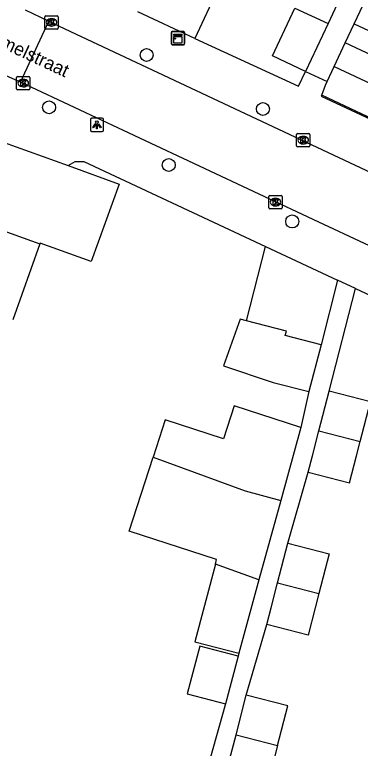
# Model space of a CAD drawing. Extents: x 159822 to 160765, y 380693 to 381634.
# Drawn here: x 160181.4 to 160207.5, y 381227.9 to 381283.3 of the extents above; entities that cross this region are included whole.
import ezdxf

# ---------------------------------------------------------------- set-up
doc = ezdxf.new("R2010")
doc.units = 0
for name, color, linetype in [('IMGEO_Boom', 7, 'Continuous'), ('IMGEO_Kast', 7, 'Continuous'), ('IMGEO_Kolk', 7, 'Continuous'), ('IMGEO_Lichtpunt', 7, 'Continuous'), ('IMGEO_Muur', 7, 'Continuous'), ('IMGEO_Openbare_ruimte_label', 7, 'Continuous'), ('IMGEO_Pand', 7, 'Continuous'), ('IMGEO_Rijbaan_lokaal_open', 7, 'Continuous'), ('IMGEO_Voetpad_halfverhard', 7, 'Continuous'), ('IMGEO_Voetpad_open', 7, 'Continuous')]:
    doc.layers.add(name, color=color, linetype=linetype)

msp = doc.modelspace()

# ---------------------------------------------------------------- linework, layer by layer
at = {"layer": 'IMGEO_Boom'}
for centre in [(160191.397, 381280.228), (160184.034, 381276.28), (160200.168, 381276.158), (160193.06, 381271.931), (160202.378, 381267.672)]:
    msp.add_circle(centre, 0.489, dxfattribs=at)
at = {"layer": 'IMGEO_Kast'}
for p, q in [((160193.337, 381282.002), (160194.178, 381282.002)), ((160194.178, 381282.002), (160193.337, 381282.002)), ((160193.262, 381281.077), (160193.262, 381281.918)), ((160193.262, 381281.918), (160193.262, 381281.077)), ((160194.262, 381281.927), (160194.262, 381281.086)), ((160194.262, 381281.086), (160194.262, 381281.927)), ((160194.187, 381281.002), (160193.346, 381281.002)), ((160193.346, 381281.002), (160194.187, 381281.002))]:
    msp.add_line(p, q, dxfattribs=at)
for points in [[(160193.457, 381281.792), (160194.057, 381281.792), (160194.057, 381281.707), (160193.457, 381281.707), (160193.457, 381281.792)], [(160193.457, 381281.617), (160194.057, 381281.617), (160194.057, 381281.128), (160193.457, 381281.128), (160193.457, 381281.617)]]:
    msp.add_lwpolyline(points, dxfattribs=at)
msp.add_circle((160193.541, 381281.466), 0.0377, dxfattribs=at)
for centre, start, end in [((160193.34, 381281.924), 92.4484, 184.2845), ((160193.34, 381281.924), 92.4484, 184.2845), ((160194.184, 381281.924), 2.4484, 94.2845), ((160194.184, 381281.924), 2.4484, 94.2845), ((160193.34, 381281.08), 182.4484, 274.2845), ((160193.34, 381281.08), 182.4484, 274.2845), ((160194.184, 381281.08), 272.4484, 4.2845), ((160194.184, 381281.08), 272.4484, 4.2845)]:
    msp.add_arc(centre, 0.0779, start, end, dxfattribs=at)
at = {"layer": 'IMGEO_Kolk'}
for p, q in [((160183.72, 381282.262), (160183.72, 381283.114)), ((160183.795, 381283.188), (160184.647, 381283.188)), ((160184.721, 381283.114), (160184.721, 381282.262)), ((160184.208, 381282.968), (160184.233, 381282.968)), ((160184.647, 381282.188), (160183.795, 381282.188)), ((160184.231, 381282.408), (160184.206, 381282.408)), ((160181.589, 381277.685), (160181.589, 381278.537)), ((160181.664, 381278.611), (160182.516, 381278.611)), ((160182.077, 381278.391), (160182.102, 381278.391)), ((160182.59, 381278.537), (160182.59, 381277.685)), ((160182.516, 381277.611), (160181.664, 381277.611)), ((160182.1, 381277.831), (160182.075, 381277.831)), ((160202.703, 381273.382), (160202.703, 381274.234)), ((160202.778, 381274.308), (160203.63, 381274.308)), ((160203.704, 381274.234), (160203.704, 381273.382)), ((160203.191, 381274.088), (160203.216, 381274.088)), ((160203.63, 381273.308), (160202.778, 381273.308)), ((160203.214, 381273.528), (160203.189, 381273.528)), ((160200.614, 381268.707), (160200.614, 381269.559)), ((160200.689, 381269.633), (160201.541, 381269.633)), ((160201.102, 381269.413), (160201.127, 381269.413)), ((160201.615, 381269.559), (160201.615, 381268.707)), ((160201.125, 381268.853), (160201.1, 381268.853)), ((160201.541, 381268.633), (160200.689, 381268.633))]:
    msp.add_line(p, q, dxfattribs=at)
for points in [[(160183.72, 381282.262), (160183.72, 381283.114)], [(160183.795, 381283.188), (160184.647, 381283.188)], [(160184.721, 381283.114), (160184.721, 381282.262)], [(160184.041, 381282.888), (160184.164, 381282.888), (160184.164, 381282.737), (160184.294, 381282.888), (160184.458, 381282.888), (160184.312, 381282.737), (160184.465, 381282.488), (160184.313, 381282.488), (160184.228, 381282.652), (160184.164, 381282.585), (160184.164, 381282.488), (160184.041, 381282.488), (160184.041, 381282.888)], [(160184.647, 381282.188), (160183.795, 381282.188)], [(160181.589, 381277.685), (160181.589, 381278.537)], [(160181.664, 381278.611), (160182.516, 381278.611)], [(160181.91, 381278.311), (160182.033, 381278.311), (160182.033, 381278.16), (160182.163, 381278.311), (160182.327, 381278.311), (160182.181, 381278.16), (160182.334, 381277.911), (160182.182, 381277.911), (160182.097, 381278.075), (160182.033, 381278.008), (160182.033, 381277.911), (160181.91, 381277.911), (160181.91, 381278.311)], [(160182.59, 381278.537), (160182.59, 381277.685)], [(160182.516, 381277.611), (160181.664, 381277.611)], [(160202.703, 381273.382), (160202.703, 381274.234)], [(160202.778, 381274.308), (160203.63, 381274.308)], [(160203.704, 381274.234), (160203.704, 381273.382)], [(160203.024, 381274.008), (160203.147, 381274.008), (160203.147, 381273.857), (160203.277, 381274.008), (160203.441, 381274.008), (160203.295, 381273.857), (160203.448, 381273.608), (160203.296, 381273.608), (160203.211, 381273.772), (160203.147, 381273.705), (160203.147, 381273.608), (160203.024, 381273.608), (160203.024, 381274.008)], [(160203.63, 381273.308), (160202.778, 381273.308)], [(160200.614, 381268.707), (160200.614, 381269.559)], [(160200.689, 381269.633), (160201.541, 381269.633)], [(160200.935, 381269.333), (160201.058, 381269.333), (160201.058, 381269.182), (160201.188, 381269.333), (160201.352, 381269.333), (160201.206, 381269.182), (160201.359, 381268.933), (160201.207, 381268.933), (160201.122, 381269.097), (160201.058, 381269.03), (160201.058, 381268.933), (160200.935, 381268.933), (160200.935, 381269.333)], [(160201.615, 381269.559), (160201.615, 381268.707)], [(160201.541, 381268.633), (160200.689, 381268.633)]]:
    msp.add_lwpolyline(points, dxfattribs=at)
for centre, start, end in [((160183.797, 381283.112), 91.552, 178.448), ((160183.797, 381283.112), 91.552, 178.448), ((160184.645, 381283.112), 1.552, 88.448), ((160184.645, 381283.112), 1.552, 88.448), ((160183.797, 381282.264), 181.552, 268.448), ((160183.797, 381282.264), 181.552, 268.448), ((160184.645, 381282.264), 271.552, 358.448), ((160184.645, 381282.264), 271.552, 358.448), ((160181.666, 381278.535), 91.552, 178.448), ((160181.666, 381278.535), 91.552, 178.448), ((160182.514, 381278.535), 1.552, 88.448), ((160182.514, 381278.535), 1.552, 88.448), ((160181.666, 381277.687), 181.552, 268.448), ((160181.666, 381277.687), 181.552, 268.448), ((160182.514, 381277.687), 271.552, 358.448), ((160182.514, 381277.687), 271.552, 358.448), ((160202.78, 381274.232), 91.552, 178.448), ((160202.78, 381274.232), 91.552, 178.448), ((160203.628, 381274.232), 1.552, 88.448), ((160203.628, 381274.232), 1.552, 88.448), ((160202.78, 381273.384), 181.552, 268.448), ((160202.78, 381273.384), 181.552, 268.448), ((160203.628, 381273.384), 271.552, 358.448), ((160203.628, 381273.384), 271.552, 358.448), ((160200.691, 381269.557), 91.552, 178.448), ((160200.691, 381269.557), 91.552, 178.448), ((160201.539, 381269.557), 1.552, 88.448), ((160201.539, 381269.557), 1.552, 88.448), ((160200.691, 381268.709), 181.552, 268.448), ((160200.691, 381268.709), 181.552, 268.448), ((160201.539, 381268.709), 271.552, 358.448), ((160201.539, 381268.709), 271.552, 358.448)]:
    msp.add_arc(centre, 0.0765, start, end, dxfattribs=at)
for centre, major_axis, ratio, start_param, end_param in [((160184.207, 381282.688), (-0.387, 0.002), 0.722429, 4.712389, 7.853982), ((160184.232, 381282.688), (-0.39, 0.002), 0.717154, 1.570796, 4.712389), ((160182.076, 381278.111), (-0.387, 0.002), 0.722429, 4.712389, 7.853982), ((160182.101, 381278.111), (-0.39, 0.002), 0.717154, 1.570796, 4.712389), ((160203.19, 381273.808), (-0.387, 0.002), 0.722429, 4.712389, 7.853982), ((160203.215, 381273.808), (-0.39, 0.002), 0.717154, 1.570796, 4.712389), ((160201.101, 381269.133), (-0.387, 0.002), 0.722429, 4.712389, 7.853982), ((160201.126, 381269.133), (-0.39, 0.002), 0.717154, 1.570796, 4.712389)]:
    msp.add_ellipse(centre, major_axis=major_axis, ratio=ratio, start_param=start_param, end_param=end_param, dxfattribs=at)
at = {"layer": 'IMGEO_Lichtpunt'}
for p, q in [((160187.15, 381275.363), (160187.15, 381274.556)), ((160187.15, 381275.363), (160187.15, 381274.556)), ((160188.052, 381275.458), (160187.244, 381275.458)), ((160188.052, 381275.458), (160187.244, 381275.458)), ((160188.146, 381274.556), (160188.146, 381275.363)), ((160188.146, 381274.556), (160188.146, 381275.363)), ((160187.244, 381274.462), (160188.052, 381274.462)), ((160187.244, 381274.462), (160188.052, 381274.462))]:
    msp.add_line(p, q, dxfattribs=at)
for points in [[(160187.524, 381275.027), (160187.563, 381274.999), (160187.375, 381274.737), (160187.337, 381274.764), (160187.524, 381275.027)], [(160187.626, 381274.979), (160187.673, 381274.979), (160187.673, 381274.657), (160187.626, 381274.657), (160187.626, 381274.979)], [(160187.736, 381274.999), (160187.774, 381275.026), (160187.961, 381274.764), (160187.922, 381274.736), (160187.736, 381274.999)]]:
    msp.add_lwpolyline(points, dxfattribs=at)
msp.add_circle((160187.649, 381275.161), 0.0994, dxfattribs=at)
for centre, start, end in [((160187.244, 381275.363), 90, 180), ((160187.244, 381275.363), 90, 180), ((160188.052, 381275.363), 0, 90), ((160188.052, 381275.363), 0, 90), ((160187.244, 381274.556), 180, 270), ((160187.244, 381274.556), 180, 270), ((160188.052, 381274.556), 270, 0), ((160188.052, 381274.556), 270, 360)]:
    msp.add_arc(centre, 0.0946, start, end, dxfattribs=at)
at = {"layer": 'IMGEO_Muur'}
msp.add_lwpolyline([(160185.472, 381271.883), (160186.017, 381272.204), (160186.65, 381272.188), (160200.361, 381265.784)], dxfattribs=at)
at = {"layer": 'IMGEO_Pand'}
for points in [[(160194.857, 381289.201), (160195.304, 381288.991), (160194.163, 381286.554), (160196.819, 381285.312), (160195.026, 381281.48)], [(160203.391, 381278.997), (160200.901, 381280.162), (160202.585, 381283.762), (160205.076, 381282.597)], [(160207.057, 381282.582), (160207.732, 381284.025)], [(160195.026, 381281.48), (160190.736, 381283.488)], [(160205.076, 381282.597), (160203.391, 381278.997)], [(160206.381, 381281.138), (160207.057, 381282.582)], [(160207.057, 381282.582), (160212.775, 381279.925)], [(160212.775, 381279.925), (160212.092, 381278.466), (160206.381, 381281.138)], [(160205.548, 381279.354), (160209.884, 381277.322), (160208.887, 381275.196), (160204.6, 381277.205)], [(160205.023, 381278.234), (160205.548, 381279.354)], [(160204.6, 381277.205), (160204.893, 381277.957), (160205.023, 381278.234)], [(160178.596, 381274.356), (160185.472, 381271.883)], [(160185.472, 381271.883), (160189.319, 381270.499), (160187.214, 381264.647), (160183.367, 381266.03), (160183.352, 381265.987)], [(160176.477, 381268.462), (160183.352, 381265.987)], [(160183.352, 381265.987), (160181.294, 381260.262)], [(160198.919, 381260.177), (160200.361, 381265.784)], [(160200.361, 381265.784), (160205.801, 381263.242)], [(160205.801, 381263.242), (160204.55, 381258.378)], [(160198.919, 381260.177), (160198.447, 381260.298), (160197.2, 381256.779), (160200.942, 381255.53), (160203.638, 381254.836)], [(160204.55, 381258.378), (160201.853, 381259.071), (160201.938, 381259.401), (160198.919, 381260.177)], [(160204.55, 381258.378), (160203.638, 381254.836)], [(160204.389, 381251.885), (160205.158, 381254.876)], [(160207.513, 381251.081), (160208.282, 381254.072), (160205.158, 381254.876)], [(160203.021, 381252.143), (160197.997, 381253.777), (160197.187, 381251.287), (160192.802, 381252.714), (160191.883, 381249.891)], [(160203.021, 381252.143), (160201.508, 381246.63)], [(160203.583, 381248.752), (160203.904, 381250), (160204.389, 381251.885)], [(160204.389, 381251.885), (160207.513, 381251.081)], [(160203.583, 381248.752), (160206.707, 381247.948), (160207.235, 381250), (160207.513, 381251.081)], [(160196.583, 381241.83), (160196.673, 381242.165), (160190.069, 381244.314), (160191.883, 381249.891)], [(160191.883, 381249.891), (160198.824, 381247.344), (160201.508, 381246.63)], [(160201.508, 381246.63), (160199.866, 381240.65)], [(160201.265, 381240.418), (160202.034, 381243.409)], [(160202.034, 381243.409), (160205.158, 381242.605), (160204.389, 381239.614)], [(160196.583, 381241.83), (160195.031, 381235.979), (160198.348, 381235.121)], [(160199.866, 381240.65), (160196.583, 381241.83)], [(160199.866, 381240.65), (160198.348, 381235.121)], [(160200.459, 381237.285), (160200.78, 381238.533), (160201.265, 381240.418)], [(160201.265, 381240.418), (160204.389, 381239.614)], [(160204.389, 381239.614), (160204.111, 381238.533), (160203.583, 381236.481), (160200.459, 381237.285)], [(160198.297, 381234.877), (160195.405, 381235.645), (160194.451, 381232.051), (160197.344, 381231.284)], [(160198.297, 381234.877), (160197.344, 381231.284)], [(160198.141, 381228.951), (160198.91, 381231.942)], [(160201.265, 381228.147), (160202.034, 381231.138), (160198.91, 381231.942)], [(160197.335, 381225.818), (160197.656, 381227.066), (160198.141, 381228.951)], [(160198.141, 381228.951), (160201.265, 381228.147)], [(160201.265, 381228.147), (160200.987, 381227.066), (160200.459, 381225.014), (160197.335, 381225.818)]]:
    msp.add_lwpolyline(points, dxfattribs=at)
at = {"layer": 'IMGEO_Rijbaan_lokaal_open'}
for points in [[(160182.232, 381283.624), (160184.006, 381282.791)], [(160181.886, 381278.181), (160184.006, 381282.791)], [(160184.006, 381282.791), (160184.802, 381282.403), (160208.794, 381271.142), (160212.221, 381269.548), (160214.775, 381268.359)], [(160181.886, 381278.181), (160180.804, 381278.668)], [(160212.641, 381263.772), (160207.826, 381266.012), (160204.38, 381267.615), (160181.886, 381278.181)]]:
    msp.add_lwpolyline(points, dxfattribs=at)
at = {"layer": 'IMGEO_Voetpad_halfverhard'}
for points in [[(160206.238, 381285.124), (160205.076, 381282.597)], [(160205.548, 381279.354), (160206.381, 381281.138)]]:
    msp.add_lwpolyline(points, dxfattribs=at)
at = {"layer": 'IMGEO_Voetpad_open'}
for points in [[(160195.026, 381281.48), (160202.862, 381277.867), (160203.391, 381278.997)], [(160203.391, 381278.997), (160205.023, 381278.234)], [(160204.6, 381277.205), (160204.565, 381277.114), (160225.954, 381267.134)], [(160185.472, 381271.883), (160186.017, 381272.204), (160186.65, 381272.188), (160200.361, 381265.784)], [(160207.149, 381262.612), (160205.801, 381263.242)], [(160205.158, 381254.876), (160207.149, 381262.612)], [(160207.149, 381262.612), (160223.562, 381254.945), (160222.893, 381253.356), (160224.405, 381252.993)], [(160203.638, 381254.836), (160203.021, 381252.143)], [(160202.034, 381243.409), (160203.583, 381248.752)], [(160198.91, 381231.942), (160200.459, 381237.285)], [(160198.348, 381235.121), (160198.297, 381234.877)], [(160197.344, 381231.284), (160195.947, 381226.279)]]:
    msp.add_lwpolyline(points, dxfattribs=at)

# ---------------------------------------------------------------- texts
at = {"layer": 'IMGEO_Openbare_ruimte_label'}
msp.add_text('Brumelstraat', height=1, rotation=334.9727, dxfattribs=at).set_placement((160178.374, 381281.735))

doc.saveas('drawing.dxf')
